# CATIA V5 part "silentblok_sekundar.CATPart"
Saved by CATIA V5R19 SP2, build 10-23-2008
Part number: silentblok_sekundar
Bounding box of the stored display mesh (mm): x 0 to 100, y -160 to 160, z -160 to 160
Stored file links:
  C:\Users\Martiin\Desktop\9.semestr\Projekt-diplomka\3D model\silentblok_sekundar.CATPart
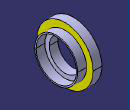
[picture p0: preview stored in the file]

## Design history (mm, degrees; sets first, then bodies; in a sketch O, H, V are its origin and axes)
Body1 (main body)
  Sketch1 on yz-plane, origin (0, 0, 0), H (0, 1, 0), V (0, 0, 1)
    circle A1 centre (0, 0) radius 160
    point P1 (0, 160)
    radius A1 = 160
    coincidence: A1 P1, P1 V
  Pad1: profile Sketch1, direction (1, 0, 0), length 50
  Sketch2 on end face of Pad1, origin (50, 0, 0), H (0, 1, 0), V (0, 0, 1)
    circle A1 centre (0, 0) radius 115
    circle A2 centre (0, 0) radius 122.5
    point P1 (0, 122.5)
    radius A1 = 115
    radius A2 = 122.5
    coincidence: A2 P1, P1 V
  Pad2: profile Sketch2, direction (1, 0, 0), length 50
  Sketch3 on end face of Pad1, origin (50, 0, 0), H (0, 1, 0), V (0, 0, 1)
    circle A1 centre (0, 0) radius 90
    radius A1 = 90
  Pocket1: profile Sketch3, direction (-1, 0, 0), through (limit type 3)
